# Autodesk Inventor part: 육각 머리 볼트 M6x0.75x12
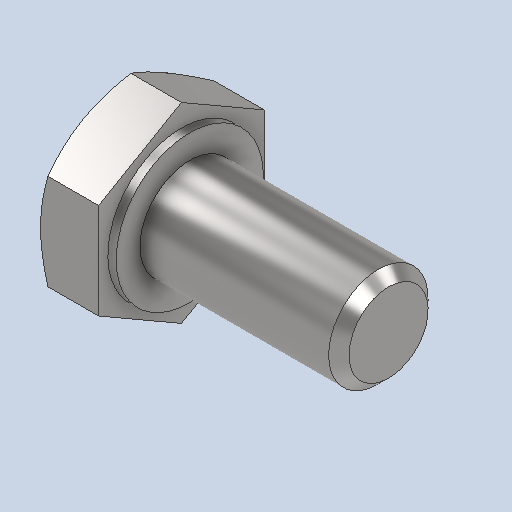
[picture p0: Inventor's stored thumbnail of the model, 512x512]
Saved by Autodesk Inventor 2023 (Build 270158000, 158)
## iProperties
Created: 2024-09
Part Number: 육각 머리 볼트 M6x0.75x12
Material: 강철, 연강
Description: 6각 머리 볼트 및 6각 머리 나사
Document SubType Name: Modeling
Designer: home
Density: 7.85 g/cm^3
Appearance: 기본값
Author: jhkim
Sending System: Autodesk Inventor 2025
Preprocessor: ST-DEVELOPER v20
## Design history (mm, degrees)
node "육각 머리 볼트 M6x0.75x121"
node "솔리드1"
body "Solid1"
